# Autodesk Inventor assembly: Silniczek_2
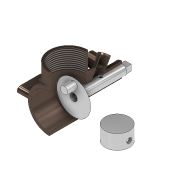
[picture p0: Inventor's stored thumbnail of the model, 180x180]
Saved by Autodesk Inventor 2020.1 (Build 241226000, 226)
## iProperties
Manager: www.cadconsulting.pl
Company: Fabian Stasiak CAD Consulting
Created: 2019-06
Part Number: Silniczek_2
Document SubType Name: Assembly
Designer: F.Stasiak
Author: F.Stasiak
Subject: Zbiór ćwiczeń. Autodesk Inventor 2020. Kurs podstawowy
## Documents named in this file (4)
- C:\2020_Kurs_podstawowy\R6 Zespoły\Wiązania\Silniczek\Silniczek_2.iam
- C:\2020_Kurs_podstawowy\R6 Zespoły\Wiązania\Silniczek\Korpus_234.ipt
- C:\2020_Kurs_podstawowy\R6 Zespoły\Wiązania\Silniczek\Wałek_234.ipt
- C:\2020_Kurs_podstawowy\R6 Zespoły\Wiązania\Silniczek\Tłok_234.ipt
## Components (3 placed, 3 different names)
1. Korpus_234:1 — Wstawiające:1, Kątowe:1
2. Wałek_234:1 — Wstawiające:1, Kątowe:1
3. Tłok_234:1
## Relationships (2: Insert 1, Angle 1)
- Wstawiające:1 [Insert]: Korpus_234:1 ↔ Wałek_234:1
- Kątowe:1 [Angle]: Korpus_234:1 ↔ Wałek_234:1
